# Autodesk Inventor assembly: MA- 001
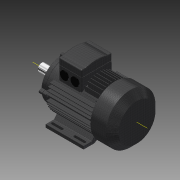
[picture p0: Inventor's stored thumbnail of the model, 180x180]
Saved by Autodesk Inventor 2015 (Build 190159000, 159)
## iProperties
Created: 2007-02
Part Number: MA- 001
Document SubType Name: Assembly
Designer: Autodesk, Inc.
Description: Motor Assembly - Custom
Mass: 7795.67 g
Surface Area: 6691.36 cm^2
Volume: 3247.34 cm^3
Density: 2.40063 g/cm^3
Author: Autodesk, Inc.
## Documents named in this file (3)
- C:\Users\Public\Documents\Autodesk\Inventor 2015\Samples\Models\Assemblies\Blower\Components\Motor Assembly.iam
- C:\Users\Public\Documents\Autodesk\Inventor 2015\Samples\Models\Assemblies\Blower\Components\ac-motor.ipt
- C:\Users\Public\Documents\Autodesk\Inventor 2015\Samples\Models\Assemblies\Blower\Motor Assembly\Design Accelerator\Shaft1.iam
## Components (2 placed, 2 different names)
1. AC Motor:1 — Mate:1, Flush:1, Angle:1
2. Shaft Design:2 [sub-assembly] — Mate:1, Flush:1, Angle:1
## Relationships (3: Mate 1, Flush 1, Angle 1)
- Mate:1: AC Motor:1 ↔ Shaft Design:2
- Flush:1: AC Motor:1 ↔ Shaft Design:2
- Angle:1: AC Motor:1 ↔ Shaft Design:2
